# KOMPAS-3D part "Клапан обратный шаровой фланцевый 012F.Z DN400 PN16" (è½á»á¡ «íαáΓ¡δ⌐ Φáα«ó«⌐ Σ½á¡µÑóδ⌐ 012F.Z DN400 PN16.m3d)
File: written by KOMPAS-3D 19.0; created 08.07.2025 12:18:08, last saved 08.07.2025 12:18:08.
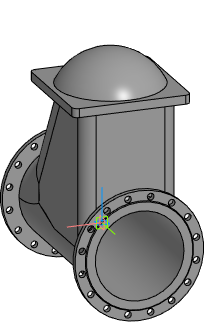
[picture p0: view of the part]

Document properties: Полное имя файла: E:\Dendor Работа Сачек\3D для проектировщиков\5.3 Тип 012F, 012F.Z Клапан обратный шаровой фланцевый\stp_Клапан обратный шаровой фланцевый 012F.Z PN10_16\Клапан обратный шаровой фланцевый 012F.Z DN400 PN16.m3d

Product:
- Part/product: Клапан обратный шаровой фланцевый 012F.Z DN400 PN16

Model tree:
1. Операция без истории:1  (labels: Клапан обратный шаровой фланцевый 012F.Z DN400 PN16)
